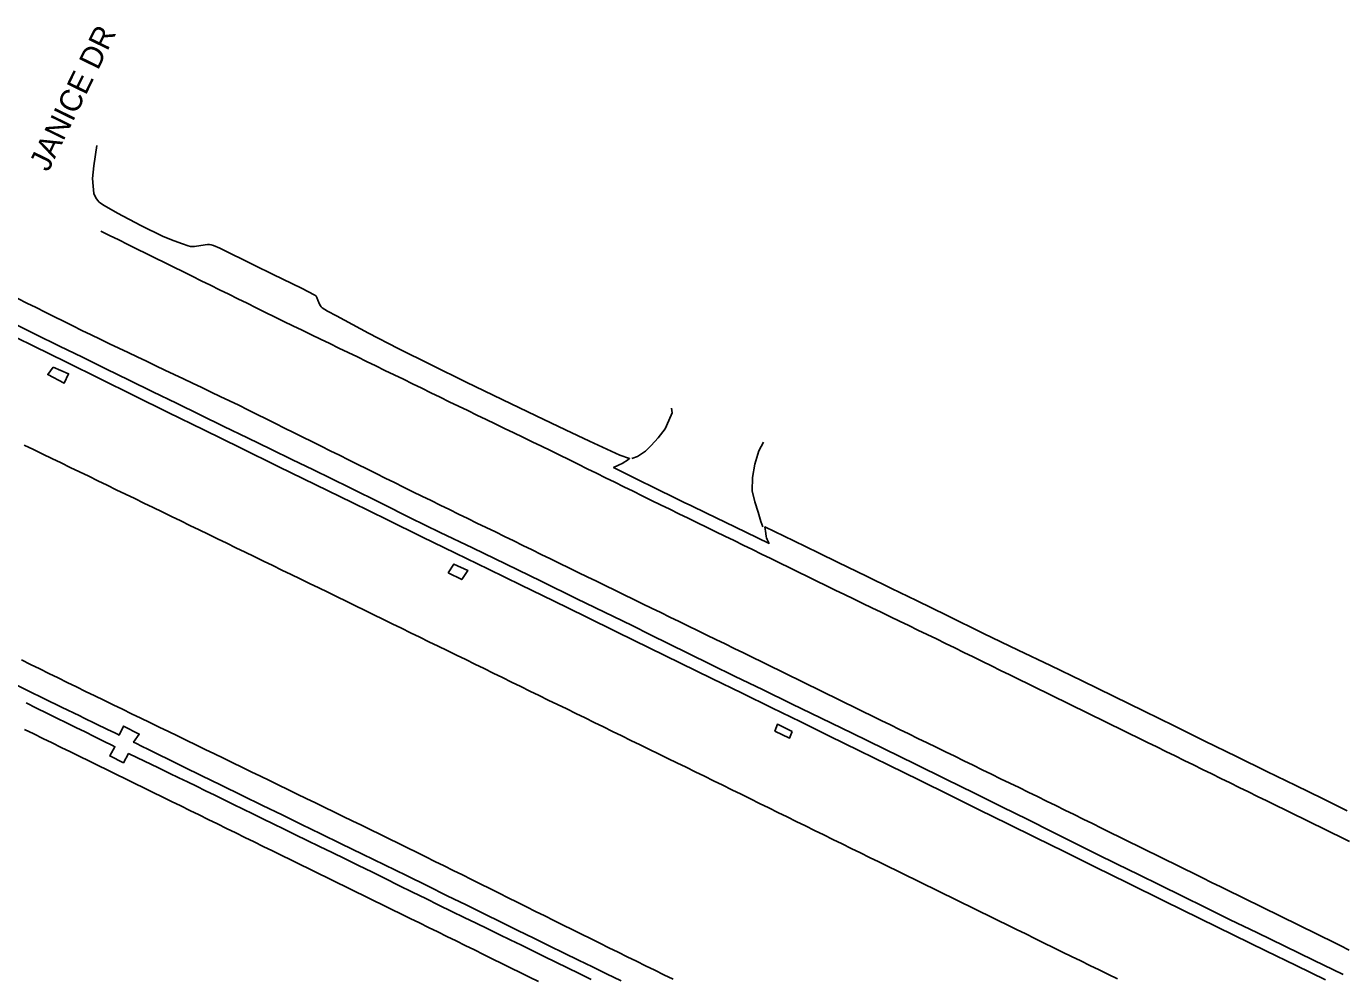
# Model space of a CAD drawing. Extents: x 1948091 to 1975253, y 787267 to 823306.
# Drawn here: x 1973301.2 to 1973623.1, y 794369.4 to 794602.2 of the extents above; entities that cross this region are included whole.
import ezdxf

# ---------------------------------------------------------------- set-up
doc = ezdxf.new("R2010")
doc.units = 0
for name, color, linetype in [('RD_EX_Pavement_Markings', 7, 'Continuous'), ('RD_EX_Road', 7, 'Continuous'), ('RD_TX_RoadID', 7, 'Continuous')]:
    doc.layers.add(name, color=color, linetype=linetype)

msp = doc.modelspace()

# ---------------------------------------------------------------- linework, layer by layer
at = {"layer": 'RD_EX_Pavement_Markings'}
for points in [[(1973624.77, 794402.98), (1973622.52, 794404.07), (1973620.28, 794405.17), (1973618.03, 794406.27), (1973615.78, 794407.37), (1973613.54, 794408.46), (1973611.29, 794409.56), (1973609.05, 794410.66), (1973606.8, 794411.75), (1973604.55, 794412.85), (1973602.31, 794413.95), (1973600.06, 794415.05), (1973597.82, 794416.15), (1973595.57, 794417.25), (1973593.33, 794418.35), (1973591.08, 794419.45), (1973588.84, 794420.55), (1973586.59, 794421.65), (1973584.35, 794422.75), (1973582.1, 794423.85), (1973579.86, 794424.95), (1973577.62, 794426.05), (1973575.37, 794427.15), (1973573.13, 794428.25), (1973570.88, 794429.35), (1973568.64, 794430.45), (1973566.39, 794431.55), (1973564.15, 794432.65), (1973561.9, 794433.75), (1973559.66, 794434.85), (1973557.42, 794435.95), (1973555.17, 794437.06), (1973552.93, 794438.16), (1973550.68, 794439.26), (1973548.44, 794440.36), (1973546.2, 794441.46), (1973543.95, 794442.56), (1973541.71, 794443.67), (1973539.46, 794444.77), (1973537.22, 794445.87), (1973534.98, 794446.97), (1973532.73, 794448.07), (1973530.49, 794449.17), (1973528.24, 794450.26), (1973525.99, 794451.35), (1973523.74, 794452.44), (1973521.49, 794453.53), (1973519.24, 794454.62), (1973516.99, 794455.7), (1973514.74, 794456.79), (1973512.48, 794457.88), (1973510.23, 794458.97), (1973507.98, 794460.06), (1973505.73, 794461.14), (1973503.48, 794462.23), (1973501.23, 794463.32), (1973498.98, 794464.41), (1973496.73, 794465.5), (1973494.48, 794466.59), (1973492.24, 794467.69), (1973489.99, 794468.79), (1973487.75, 794469.88), (1973485.5, 794470.98), (1973483.26, 794472.08), (1973481.01, 794473.18), (1973478.77, 794474.28), (1973476.52, 794475.38), (1973474.28, 794476.48), (1973472.03, 794477.58), (1973469.78, 794478.67), (1973467.53, 794479.77), (1973465.28, 794480.86), (1973463.04, 794481.95), (1973460.79, 794483.05), (1973458.54, 794484.14), (1973456.29, 794485.23), (1973454.04, 794486.33), (1973451.8, 794487.42), (1973449.56, 794488.53), (1973447.31, 794489.63), (1973445.07, 794490.74), (1973442.83, 794491.85), (1973440.59, 794492.95), (1973438.35, 794494.06), (1973436.1, 794495.16), (1973433.86, 794496.27), (1973431.62, 794497.37), (1973429.38, 794498.48), (1973427.13, 794499.57), (1973424.88, 794500.66), (1973422.63, 794501.75), (1973420.37, 794502.83), (1973418.12, 794503.92), (1973415.87, 794505.01), (1973413.62, 794506.09), (1973411.37, 794507.18), (1973409.12, 794508.27), (1973406.87, 794509.35), (1973404.62, 794510.44), (1973402.37, 794511.53), (1973400.12, 794512.63), (1973397.87, 794513.72), (1973395.62, 794514.81), (1973393.38, 794515.91), (1973391.13, 794517), (1973388.88, 794518.1), (1973386.63, 794519.19), (1973384.38, 794520.28), (1973382.13, 794521.37), (1973379.88, 794522.46), (1973377.63, 794523.54), (1973375.38, 794524.63), (1973373.13, 794525.72), (1973370.88, 794526.81), (1973368.63, 794527.9), (1973366.38, 794528.98), (1973364.12, 794530.07), (1973361.88, 794531.17), (1973359.64, 794532.27), (1973357.39, 794533.38), (1973355.15, 794534.49), (1973352.91, 794535.6), (1973350.67, 794536.7), (1973348.43, 794537.81), (1973346.19, 794538.92), (1973343.95, 794540.02), (1973341.7, 794541.13), (1973339.46, 794542.24), (1973337.22, 794543.34), (1973334.98, 794544.45), (1973332.73, 794545.55), (1973330.49, 794546.66), (1973328.25, 794547.76), (1973326.01, 794548.87), (1973323.76, 794549.97), (1973321.52, 794551.08), (1973319.37, 794552.13)], [(1973299.09, 794535.65), (1973301.33, 794534.54), (1973303.57, 794533.43), (1973305.81, 794532.32), (1973308.05, 794531.2), (1973310.29, 794530.09), (1973312.52, 794528.98), (1973314.76, 794527.87), (1973317.01, 794526.77), (1973319.27, 794525.69), (1973321.52, 794524.62), (1973323.78, 794523.54), (1973326.04, 794522.47), (1973328.29, 794521.39), (1973330.55, 794520.32), (1973332.81, 794519.24), (1973335.07, 794518.17), (1973337.32, 794517.1), (1973339.58, 794516.02), (1973341.84, 794514.95), (1973344.09, 794513.87), (1973346.35, 794512.8), (1973348.61, 794511.72), (1973350.87, 794510.65), (1973353.12, 794509.56), (1973355.36, 794508.45), (1973357.6, 794507.34), (1973359.83, 794506.23), (1973362.07, 794505.11), (1973364.31, 794504), (1973366.55, 794502.89), (1973368.79, 794501.78), (1973371.03, 794500.67), (1973373.27, 794499.55), (1973375.51, 794498.44), (1973377.75, 794497.33), (1973379.99, 794496.22), (1973382.23, 794495.11), (1973384.46, 794494), (1973386.7, 794492.88), (1973388.94, 794491.77), (1973391.18, 794490.66), (1973393.42, 794489.55), (1973395.66, 794488.44), (1973397.91, 794487.34), (1973400.16, 794486.25), (1973402.4, 794485.16), (1973404.65, 794484.06), (1973406.9, 794482.97), (1973409.15, 794481.87), (1973411.39, 794480.78), (1973413.64, 794479.68), (1973415.89, 794478.59), (1973418.13, 794477.49), (1973420.38, 794476.4), (1973422.63, 794475.3), (1973424.88, 794474.21), (1973427.12, 794473.11), (1973429.37, 794472.02), (1973431.62, 794470.92), (1973433.87, 794469.83), (1973436.11, 794468.73), (1973438.36, 794467.64), (1973440.61, 794466.54), (1973442.86, 794465.45), (1973445.1, 794464.35), (1973447.35, 794463.26), (1973449.6, 794462.16), (1973451.85, 794461.07), (1973454.09, 794459.97), (1973456.34, 794458.88), (1973458.59, 794457.79), (1973460.83, 794456.69), (1973463.08, 794455.6), (1973465.33, 794454.5), (1973467.58, 794453.41), (1973469.82, 794452.31), (1973472.07, 794451.22), (1973474.32, 794450.12), (1973476.56, 794449.02), (1973478.81, 794447.92), (1973481.05, 794446.82), (1973483.3, 794445.72), (1973485.54, 794444.62), (1973487.79, 794443.53), (1973490.03, 794442.43), (1973492.28, 794441.33), (1973494.52, 794440.23), (1973496.77, 794439.13), (1973499.01, 794438.03), (1973501.26, 794436.93), (1973503.5, 794435.83), (1973505.75, 794434.73), (1973507.99, 794433.63), (1973510.24, 794432.53), (1973512.49, 794431.44), (1973514.73, 794430.34), (1973516.98, 794429.24), (1973519.23, 794428.15), (1973521.47, 794427.05), (1973523.72, 794425.96), (1973525.97, 794424.86), (1973528.22, 794423.77), (1973530.46, 794422.67), (1973532.71, 794421.58), (1973534.96, 794420.48), (1973537.2, 794419.39), (1973539.45, 794418.29), (1973541.7, 794417.2), (1973543.95, 794416.1), (1973546.19, 794415.01), (1973548.44, 794413.91), (1973550.69, 794412.82), (1973552.93, 794411.72), (1973555.17, 794410.61), (1973557.42, 794409.51), (1973559.66, 794408.41), (1973561.9, 794407.3), (1973564.15, 794406.2), (1973566.39, 794405.09), (1973568.63, 794403.99), (1973570.87, 794402.89), (1973573.12, 794401.78), (1973575.36, 794400.68), (1973577.6, 794399.57), (1973579.85, 794398.47), (1973582.09, 794397.37), (1973584.33, 794396.26), (1973586.57, 794395.16), (1973588.82, 794394.06), (1973591.06, 794392.95), (1973593.3, 794391.85), (1973595.55, 794390.74), (1973597.79, 794389.64), (1973600.04, 794388.54), (1973602.28, 794387.44), (1973604.52, 794386.34), (1973606.77, 794385.24), (1973609.01, 794384.13), (1973611.25, 794383.03), (1973613.5, 794381.93), (1973615.74, 794380.83), (1973617.99, 794379.73), (1973620.23, 794378.63), (1973622.47, 794377.52), (1973624.72, 794376.42)], [(1973568.04, 794369.37), (1973565.8, 794370.46), (1973563.55, 794371.56), (1973561.3, 794372.65), (1973559.05, 794373.74), (1973556.8, 794374.84), (1973554.56, 794375.93), (1973552.31, 794377.03), (1973550.07, 794378.13), (1973547.82, 794379.23), (1973545.58, 794380.34), (1973543.33, 794381.44), (1973541.09, 794382.54), (1973538.84, 794383.64), (1973536.6, 794384.74), (1973534.36, 794385.84), (1973532.11, 794386.94), (1973529.87, 794388.04), (1973527.62, 794389.14), (1973525.38, 794390.24), (1973523.13, 794391.34), (1973520.89, 794392.45), (1973518.64, 794393.55), (1973516.4, 794394.65), (1973514.15, 794395.75), (1973511.91, 794396.85), (1973509.67, 794397.95), (1973507.42, 794399.05), (1973505.18, 794400.15), (1973502.93, 794401.25), (1973500.69, 794402.35), (1973498.44, 794403.46), (1973496.2, 794404.56), (1973493.95, 794405.66), (1973491.71, 794406.76), (1973489.47, 794407.86), (1973487.22, 794408.96), (1973484.98, 794410.06), (1973482.73, 794411.16), (1973480.49, 794412.26), (1973478.24, 794413.36), (1973476, 794414.47), (1973473.75, 794415.57), (1973471.51, 794416.67), (1973469.26, 794417.77), (1973467.02, 794418.87), (1973464.78, 794419.97), (1973462.53, 794421.07), (1973460.28, 794422.17), (1973458.04, 794423.26), (1973455.79, 794424.36), (1973453.54, 794425.46), (1973451.3, 794426.55), (1973449.05, 794427.65), (1973446.8, 794428.75), (1973444.56, 794429.84), (1973442.31, 794430.94), (1973440.07, 794432.04), (1973437.82, 794433.14), (1973435.57, 794434.23), (1973433.33, 794435.33), (1973431.08, 794436.43), (1973428.83, 794437.52), (1973426.59, 794438.62), (1973424.34, 794439.72), (1973422.09, 794440.81), (1973419.85, 794441.91), (1973417.6, 794443.01), (1973415.35, 794444.11), (1973413.11, 794445.2), (1973410.86, 794446.3), (1973408.62, 794447.4), (1973406.37, 794448.49), (1973404.12, 794449.59), (1973401.88, 794450.69), (1973399.63, 794451.78), (1973397.38, 794452.88), (1973395.14, 794453.98), (1973392.89, 794455.08), (1973390.64, 794456.17), (1973388.4, 794457.27), (1973386.15, 794458.37), (1973383.9, 794459.46), (1973381.66, 794460.56), (1973379.41, 794461.66), (1973377.16, 794462.75), (1973374.92, 794463.85), (1973372.67, 794464.94), (1973370.42, 794466.03), (1973368.17, 794467.12), (1973365.92, 794468.21), (1973363.67, 794469.3), (1973361.42, 794470.39), (1973359.17, 794471.48), (1973356.92, 794472.57), (1973354.67, 794473.66), (1973352.42, 794474.75), (1973350.17, 794475.84), (1973347.92, 794476.93), (1973345.67, 794478.02), (1973343.42, 794479.11), (1973341.17, 794480.21), (1973338.92, 794481.3), (1973336.67, 794482.39), (1973334.42, 794483.48), (1973332.17, 794484.57), (1973329.92, 794485.66), (1973327.67, 794486.75), (1973325.42, 794487.84), (1973323.17, 794488.93), (1973320.93, 794490.02), (1973318.68, 794491.11), (1973316.43, 794492.2), (1973314.18, 794493.29), (1973311.93, 794494.38), (1973309.68, 794495.47), (1973307.43, 794496.56), (1973305.18, 794497.65), (1973302.93, 794498.74), (1973300.68, 794499.83)], [(1973299.95, 794447.32), (1973302.19, 794446.22), (1973304.44, 794445.13), (1973306.68, 794444.03), (1973308.93, 794442.93), (1973311.17, 794441.83), (1973313.42, 794440.73), (1973315.67, 794439.63), (1973317.91, 794438.54), (1973320.16, 794437.45), (1973322.41, 794436.36), (1973324.66, 794435.27), (1973326.91, 794434.18), (1973329.16, 794433.09), (1973331.41, 794432), (1973333.66, 794430.91), (1973335.91, 794429.82), (1973338.16, 794428.73), (1973340.41, 794427.64), (1973342.66, 794426.55), (1973344.91, 794425.46), (1973347.16, 794424.37), (1973349.41, 794423.28), (1973351.66, 794422.19), (1973353.91, 794421.09), (1973356.16, 794420), (1973358.41, 794418.91), (1973360.66, 794417.82), (1973362.9, 794416.73), (1973365.15, 794415.64), (1973367.4, 794414.54), (1973369.65, 794413.45), (1973371.9, 794412.36), (1973374.15, 794411.27), (1973376.4, 794410.18), (1973378.65, 794409.09), (1973380.9, 794407.99), (1973383.15, 794406.9), (1973385.4, 794405.81), (1973387.64, 794404.72), (1973389.89, 794403.63), (1973392.14, 794402.54), (1973394.38, 794401.43), (1973396.62, 794400.32), (1973398.86, 794399.2), (1973401.1, 794398.09), (1973403.34, 794396.98), (1973405.58, 794395.87), (1973407.82, 794394.76), (1973410.06, 794393.65), (1973412.3, 794392.54), (1973414.54, 794391.42), (1973416.78, 794390.31), (1973419.02, 794389.2), (1973421.25, 794388.09), (1973423.49, 794386.98), (1973425.73, 794385.87), (1973427.97, 794384.75), (1973430.21, 794383.64), (1973432.45, 794382.53), (1973434.69, 794381.42), (1973436.93, 794380.31), (1973439.17, 794379.2), (1973441.41, 794378.09), (1973443.65, 794376.97), (1973445.89, 794375.86), (1973448.13, 794374.77), (1973450.38, 794373.67), (1973452.63, 794372.57), (1973454.87, 794371.48), (1973457.12, 794370.38), (1973459.37, 794369.29)], [(1973300.75, 794430.32), (1973303, 794429.23), (1973305.24, 794428.13), (1973307.49, 794427.03), (1973309.73, 794425.93), (1973311.98, 794424.83), (1973314.23, 794423.73), (1973316.47, 794422.63), (1973318.72, 794421.53), (1973320.96, 794420.43), (1973323.21, 794419.33), (1973325.45, 794418.23), (1973327.7, 794417.14), (1973329.94, 794416.04), (1973332.19, 794414.94), (1973334.43, 794413.84), (1973336.68, 794412.74), (1973338.92, 794411.64), (1973341.17, 794410.54), (1973343.41, 794409.44), (1973345.66, 794408.34), (1973347.9, 794407.24), (1973350.15, 794406.14), (1973352.39, 794405.04), (1973354.64, 794403.94), (1973356.88, 794402.84), (1973359.13, 794401.73), (1973361.37, 794400.63), (1973363.62, 794399.53), (1973365.86, 794398.43), (1973368.11, 794397.33), (1973370.35, 794396.23), (1973372.6, 794395.13), (1973374.84, 794394.03), (1973377.09, 794392.93), (1973379.33, 794391.83), (1973381.58, 794390.73), (1973383.82, 794389.63), (1973386.06, 794388.53), (1973388.31, 794387.43), (1973390.55, 794386.33), (1973392.8, 794385.23), (1973395.04, 794384.13), (1973397.29, 794383.03), (1973399.53, 794381.93), (1973401.78, 794380.83), (1973404.02, 794379.73), (1973406.27, 794378.63), (1973408.51, 794377.53), (1973410.76, 794376.43), (1973413, 794375.32), (1973415.25, 794374.22), (1973417.49, 794373.12), (1973419.74, 794372.02), (1973421.98, 794370.92), (1973424.23, 794369.82), (1973426.47, 794368.72)]]:
    msp.add_lwpolyline(points, dxfattribs=at)
at = {"layer": 'RD_EX_Road'}
for points in [[(1973624.17, 794410.44), (1973618.14, 794413.42), (1973611.63, 794416.61), (1973604.57, 794420.06), (1973597.13, 794423.7), (1973589.42, 794427.5), (1973581.88, 794431.2), (1973574.54, 794434.78), (1973567.04, 794438.44), (1973559.36, 794442.21), (1973551.61, 794445.95), (1973543.74, 794449.72), (1973535.25, 794453.82), (1973526.36, 794458.17), (1973518.85, 794461.83), (1973512.77, 794464.79), (1973506.65, 794467.78), (1973499.74, 794471.16), (1973494.88, 794473.52), (1973488.89, 794476.42), (1973481.79, 794479.84), (1973482.01, 794478.23), (1973482.11, 794477.51), (1973482.19, 794477.15), (1973482.34, 794476.75), (1973482.56, 794476.29), (1973482.84, 794475.8), (1973477.15, 794478.53), (1973472.05, 794480.98), (1973467.55, 794483.16), (1973463.65, 794485.06), (1973462.07, 794485.84), (1973459.77, 794486.97), (1973455.33, 794489.15), (1973450.35, 794491.62), (1973444.81, 794494.36), (1973446.01, 794494.89), (1973447.06, 794495.43), (1973447.42, 794495.65), (1973447.96, 794495.98), (1973448.71, 794496.56), (1973446.34, 794497.37), (1973438.91, 794500.8), (1973433.06, 794503.55), (1973425.87, 794506.96), (1973417.53, 794510.96), (1973408.74, 794515.23), (1973400.17, 794519.43), (1973392.13, 794523.46), (1973384.89, 794527.22), (1973377.02, 794531.39), (1973374.84, 794532.59), (1973373.49, 794533.41), (1973373.39, 794533.51), (1973373.29, 794533.62), (1973373.09, 794533.9), (1973372.88, 794534.27), (1973372.44, 794535.27), (1973372.2, 794535.93), (1973372.12, 794536.1), (1973372.04, 794536.24), (1973371.96, 794536.35), (1973371.75, 794536.5), (1973368.47, 794538.18), (1973361.51, 794541.53), (1973356.86, 794543.82), (1973348.5, 794547.96), (1973346.93, 794548.63), (1973346.37, 794548.79), (1973345.89, 794548.87), (1973345.5, 794548.86), (1973343.85, 794548.62), (1973342.29, 794548.39), (1973341.98, 794548.37), (1973341.67, 794548.37), (1973341.36, 794548.41), (1973340.72, 794548.57), (1973339.34, 794549.05), (1973337.33, 794549.77), (1973334.6, 794550.85), (1973329.17, 794553.54), (1973323.46, 794556.51), (1973320.19, 794558.36), (1973319.28, 794558.98), (1973318.94, 794559.26), (1973318.64, 794559.59), (1973318.33, 794560.04), (1973318.01, 794560.61), (1973317.69, 794561.29), (1973317.51, 794563.11), (1973317.32, 794564.98), (1973317.66, 794568.12), (1973318.4, 794573.07)], [(1973623.2, 794370.42), (1973616, 794373.92), (1973608.92, 794377.37), (1973602.08, 794380.69), (1973595.63, 794383.83), (1973589.57, 794386.79), (1973583.9, 794389.57), (1973578.47, 794392.24), (1973573.15, 794394.86), (1973567.94, 794397.43), (1973562.84, 794399.96), (1973557.61, 794402.55), (1973552.02, 794405.32), (1973546.07, 794408.28), (1973539.75, 794411.42), (1973533.08, 794414.73), (1973526.05, 794418.19), (1973518.66, 794421.81), (1973510.93, 794425.59), (1973503.13, 794429.39), (1973495.58, 794433.06), (1973488.27, 794436.62), (1973481.21, 794440.06), (1973474.57, 794443.29), (1973468.54, 794446.24), (1973463.12, 794448.89), (1973458.31, 794451.26), (1973453.81, 794453.48), (1973449.31, 794455.7), (1973444.81, 794457.9), (1973435.84, 794462.26), (1973427.06, 794466.54), (1973418.5, 794470.71), (1973410.26, 794474.69), (1973402.39, 794478.46), (1973395.06, 794482.05), (1973388.09, 794485.55), (1973380.23, 794489.45), (1973375.88, 794491.57), (1973371.23, 794493.83), (1973366.25, 794496.26), (1973360.94, 794498.84), (1973355.3, 794501.58), (1973349.5, 794504.4), (1973343.69, 794507.22), (1973337.89, 794510.05), (1973332.1, 794512.88), (1973326.33, 794515.7), (1973320.6, 794518.51), (1973314.93, 794521.29), (1973309.3, 794524.05), (1973303.37, 794526.96), (1973296.81, 794530.17)], [(1973618.91, 794369.16), (1973611.7, 794372.65), (1973604.33, 794376.23), (1973596.48, 794380.06), (1973588.17, 794384.13), (1973579.39, 794388.46), (1973570.67, 794392.76), (1973562.53, 794396.78), (1973554.97, 794400.5), (1973547.99, 794403.93), (1973541.2, 794407.27), (1973534.2, 794410.71), (1973527, 794414.26), (1973519.58, 794417.91), (1973512.13, 794421.57), (1973504.81, 794425.17), (1973497.62, 794428.69), (1973490.57, 794432.15), (1973483.49, 794435.62), (1973476.23, 794439.17), (1973468.8, 794442.81), (1973461.19, 794446.54), (1973453.47, 794450.31), (1973445.71, 794454.1), (1973437.92, 794457.91), (1973430.09, 794461.73), (1973422.19, 794465.58), (1973414.2, 794469.48), (1973406.11, 794473.43), (1973397.92, 794477.44), (1973389.54, 794481.54), (1973380.89, 794485.78), (1973371.96, 794490.14), (1973362.75, 794494.63), (1973353.53, 794499.14), (1973344.57, 794503.53), (1973335.88, 794507.8), (1973327.45, 794511.96), (1973319.19, 794516.04), (1973310.99, 794520.08), (1973302.87, 794524.06), (1973294.82, 794528.01)], [(1973307.72, 794518.91), (1973306.42, 794517.05), (1973310.41, 794514.95), (1973311.52, 794517.27), (1973307.72, 794518.91)], [(1973459, 794508.88), (1973459.09, 794507.74), (1973458.34, 794505.84), (1973457.4, 794503.81), (1973455.73, 794501.62), (1973453.97, 794499.75), (1973452.56, 794498.33), (1973450.64, 794497.08), (1973449.24, 794496.52)], [(1973481.42, 794500.56), (1973480.34, 794498.44), (1973479.32, 794495.14), (1973478.79, 794491.95), (1973478.67, 794488.67), (1973479.33, 794485.93), (1973480.12, 794483.44), (1973480.78, 794481.18), (1973481.27, 794479.88)], [(1973404.3, 794468.57), (1973407.67, 794466.97), (1973409.13, 794469.2), (1973405.76, 794470.76), (1973404.3, 794468.57)], [(1973297.88, 794441.62), (1973301.64, 794439.78), (1973305.61, 794437.83), (1973309.81, 794435.79), (1973314.23, 794433.64), (1973315.13, 794433.2), (1973318.2, 794431.71), (1973321.05, 794430.32), (1973322.8, 794429.48), (1973323.28, 794429.24), (1973323.43, 794429.17), (1973323.87, 794428.95), (1973324.95, 794431.16), (1973328.78, 794429.19), (1973327.4, 794427.21), (1973328.09, 794426.88), (1973329.33, 794426.26), (1973331.09, 794425.4), (1973333.36, 794424.28), (1973336.22, 794422.88), (1973339.74, 794421.15), (1973343.94, 794419.1), (1973348.81, 794416.72), (1973353.94, 794414.22), (1973358.93, 794411.78), (1973363.78, 794409.42), (1973368.49, 794407.11), (1973373.23, 794404.8), (1973378.19, 794402.37), (1973383.37, 794399.84), (1973388.77, 794397.21), (1973394.15, 794394.59), (1973399.27, 794392.08), (1973404.13, 794389.7), (1973408.73, 794387.43), (1973413.12, 794385.26), (1973417.34, 794383.19), (1973421.39, 794381.2), (1973425.28, 794379.29), (1973429.03, 794377.46), (1973432.67, 794375.68), (1973436.2, 794373.95), (1973439.63, 794372.28), (1973443.08, 794370.6), (1973446.67, 794368.85)], [(1973439.35, 794369.21), (1973436.41, 794370.65), (1973433.51, 794372.08), (1973430.64, 794373.48), (1973427.81, 794374.87), (1973425.02, 794376.23), (1973422.25, 794377.58), (1973419.52, 794378.91), (1973416.81, 794380.23), (1973414.07, 794381.56), (1973411.22, 794382.94), (1973408.27, 794384.38), (1973405.21, 794385.87), (1973402.07, 794387.4), (1973398.87, 794388.97), (1973395.61, 794390.57), (1973392.3, 794392.21), (1973388.97, 794393.86), (1973385.67, 794395.49), (1973382.38, 794397.1), (1973379.12, 794398.69), (1973375.93, 794400.24), (1973372.84, 794401.75), (1973369.87, 794403.2), (1973367, 794404.61), (1973364.24, 794405.96), (1973361.58, 794407.26), (1973359.03, 794408.51), (1973356.58, 794409.71), (1973354.2, 794410.88), (1973351.85, 794412.02), (1973349.53, 794413.15), (1973347.25, 794414.26), (1973344.99, 794415.35), (1973342.78, 794416.43), (1973340.61, 794417.49), (1973338.47, 794418.54), (1973336.13, 794419.68), (1973333.32, 794421.03), (1973330.05, 794422.6), (1973326.31, 794424.37), (1973326.19, 794424.43), (1973324.92, 794422.18), (1973321.57, 794423.86), (1973322.82, 794426.11), (1973322.25, 794426.39), (1973320.03, 794427.5), (1973317.79, 794428.61), (1973315.55, 794429.72), (1973313.29, 794430.83), (1973310.99, 794431.95), (1973308.62, 794433.12), (1973306.18, 794434.31), (1973303.67, 794435.55), (1973301.11, 794436.81)], [(1973488.46, 794429.81), (1973487.79, 794428.19), (1973484.27, 794429.91), (1973484.88, 794431.61), (1973488.46, 794429.81)]]:
    msp.add_lwpolyline(points, dxfattribs=at)

# ---------------------------------------------------------------- texts
at = {"layer": 'RD_TX_RoadID'}
msp.add_text('JANICE DR', height=5.4, rotation=63.9679, dxfattribs=at).set_placement((1973306.52, 794566.4))

doc.saveas('drawing.dxf')
